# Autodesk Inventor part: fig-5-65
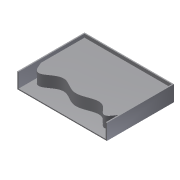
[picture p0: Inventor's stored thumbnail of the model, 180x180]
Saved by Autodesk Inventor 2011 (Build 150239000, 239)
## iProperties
Created: 2004-05
Part Number: fig-5-65
Document SubType Name: Modeling
Designer: CADCIM Technologies
Manufacturer: Standard
Standards Organization: Custom
Density: 1 g/cm^3
Author: CADCIM Technologies
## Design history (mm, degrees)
sketch "Sketch1"
  geometry: L1 (-40, -30)-(40, -30); L2 (40, -30)-(40, 30); L3 (40, 30)-(-40, 30); L4 (-40, 30)-(-40, -30); 1 further point
  constraints: 8 end point, 2 parallel, 1 horizontal, 1 perpendicular, 1 other
  dimensions: "d0" = 80 distance of L1.start L1.end; "d1" = 60 distance of L3.end L1.start; "d2" = 30 distance from line of point (0, 0) L1; "d3" = 40 distance from line of point (0, 0) L4
extrude "Extrusion1" new body sketch "Sketch1" distance "d4" = 14; taper "d5" = 0 deg
shell "Shell1" dims "d6" = 1
workplane "Work Plane1"
sketch "Sketch2"
  geometry: L1 (78, -13)-(78, -11.813); L2 (0, -11.813)-(0, -13); L3 (0, -13)-(78, -13); L4 (0, -11.813)-(17.826, -3.295); L5 (17.826, -3.295)-(60.174, -3.295); L6 (60.174, -3.295)-(78, -11.813); L7 (79, -13.795)-(78, -13.795); L8 (78, 0)-(78, -13) reference; L9 (0, -13)-(0, 0) reference; L10 (78, -13)-(0, -13) reference
  constraints: 14 end point, 3 collinear, 2 equal length, 2 vertical, 1 horizontal alignment, 1 parallel, 1 point on line
extrude "Extrusion2" join sketch "Sketch2" stored distance "d8" = 14; taper "d9" = 0 deg
workplane "Work Plane2"
sketch "Sketch4"
  geometry: 7 further points
  constraints: 7 other
extrude "Extrusion9" join sketch "Sketch4" distance "d35" = 10; taper "d36" = 0 deg
body "Solid1"
other parameters: "d7" = 23, "d18" = 4
